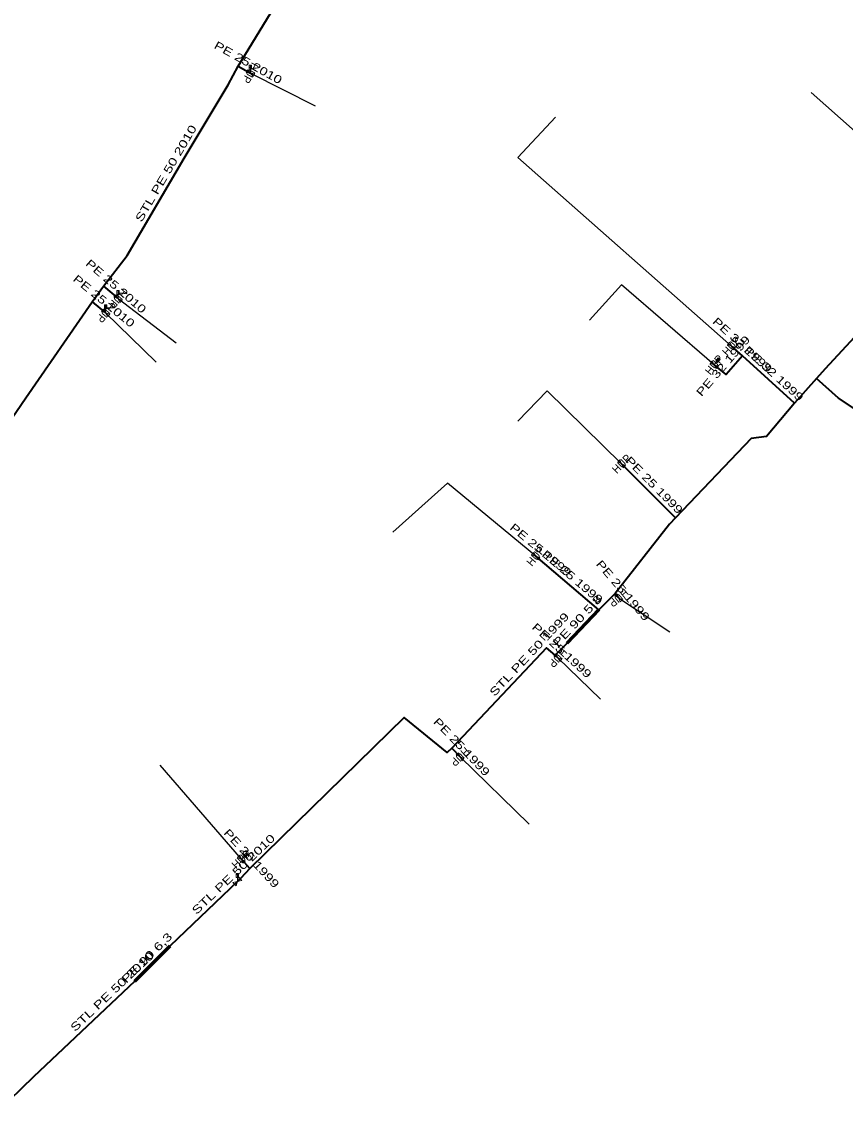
# Model space of a CAD drawing. Extents: x -737484 to -734496, y -1033882 to -1030666.
# Drawn here: x -736461.6 to -736358.7, y -1032557.9 to -1032421.6 of the extents above; entities that cross this region are included whole.
import ezdxf
from ezdxf.enums import TextEntityAlignment as Align

# ---------------------------------------------------------------- set-up
doc = ezdxf.new("R2010")
doc.units = 0
doc.header["$LTSCALE"] = 0.4
for name, color, linetype, lineweight in [('1', 7, 'Continuous', 13), ('18', 7, 'Continuous', 60), ('22', 7, 'Continuous', 25), ('5', 7, 'Continuous', 35), ('7', 7, 'Continuous', 35)]:
    doc.layers.add(name, color=color, linetype=linetype, lineweight=lineweight)
doc.layers.add('2', color=7, linetype='Continuous')

msp = doc.modelspace()

# ---------------------------------------------------------------- linework, layer by layer
at = {"layer": '1'}
for p, q in [((-736433.019, -1032428.027), (-736433.019, -1032427.527)), ((-736432.944, -1032427.452), (-736432.944, -1032427.102)), ((-736449.565, -1032456.226), (-736449.565, -1032455.726)), ((-736449.49, -1032455.651), (-736449.49, -1032455.301)), ((-736451.111, -1032457.994), (-736451.111, -1032457.494)), ((-736451.036, -1032457.419), (-736451.036, -1032457.069)), ((-736375.079, -1032464.499), (-736374.764, -1032464.11)), ((-736374.658, -1032464.099), (-736374.438, -1032463.827)), ((-736434.15, -1032526.3), (-736433.784, -1032525.959)), ((-736433.678, -1032525.962), (-736433.422, -1032525.724)), ((-736434.644, -1032529.078), (-736434.644, -1032528.578)), ((-736434.569, -1032528.503), (-736434.569, -1032528.153))]:
    msp.add_line(p, q, dxfattribs=at)
for points in [[(-736432.484, -1032428.094), (-736432.678, -1032428.444), (-736433.359, -1032427.609), (-736433.553, -1032427.959)], [(-736433.019, -1032427.027), (-736433.169, -1032427.027), (-736433.169, -1032427.527), (-736433.019, -1032427.527)], [(-736433.019, -1032427.027), (-736432.869, -1032427.027), (-736432.869, -1032427.527), (-736433.019, -1032427.527)], [(-736432.982, -1032427.065), (-736432.907, -1032427.065), (-736432.907, -1032427.49), (-736432.982, -1032427.49)], [(-736449.056, -1032456.403), (-736449.318, -1032456.704), (-736449.811, -1032455.747), (-736450.073, -1032456.048)], [(-736449.565, -1032455.226), (-736449.715, -1032455.226), (-736449.715, -1032455.726), (-736449.565, -1032455.726)], [(-736449.565, -1032455.226), (-736449.415, -1032455.226), (-736449.415, -1032455.726), (-736449.565, -1032455.726)], [(-736449.528, -1032455.264), (-736449.453, -1032455.264), (-736449.453, -1032455.689), (-736449.528, -1032455.689)], [(-736450.596, -1032458.153), (-736450.848, -1032458.464), (-736451.373, -1032457.523), (-736451.625, -1032457.834)], [(-736451.111, -1032456.994), (-736451.261, -1032456.994), (-736451.261, -1032457.494), (-736451.111, -1032457.494)], [(-736451.111, -1032456.994), (-736450.961, -1032456.994), (-736450.961, -1032457.494), (-736451.111, -1032457.494)], [(-736451.074, -1032457.032), (-736450.999, -1032457.032), (-736450.999, -1032457.457), (-736451.074, -1032457.457)], [(-736373.404, -1032461.963), (-736373.136, -1032461.665), (-736372.661, -1032462.632), (-736372.393, -1032462.334)], [(-736375.593, -1032464.339), (-736375.341, -1032464.028), (-736374.816, -1032464.969), (-736374.564, -1032464.658)], [(-736374.449, -1032463.721), (-736374.566, -1032463.627), (-736374.88, -1032464.016), (-736374.764, -1032464.11)], [(-736374.449, -1032463.721), (-736374.333, -1032463.816), (-736374.647, -1032464.204), (-736374.764, -1032464.11)], [(-736374.444, -1032463.774), (-736374.386, -1032463.821), (-736374.654, -1032464.152), (-736374.712, -1032464.104)], [(-736387.133, -1032476.666), (-736386.851, -1032476.384), (-736386.426, -1032477.373), (-736386.144, -1032477.091)], [(-736397.883, -1032488.245), (-736397.626, -1032487.939), (-736397.117, -1032488.888), (-736396.86, -1032488.582)], [(-736386.533, -1032493.874), (-736386.839, -1032494.131), (-736387.176, -1032493.108), (-736387.482, -1032493.365)], [(-736394.102, -1032501.304), (-736394.37, -1032501.602), (-736394.845, -1032500.635), (-736395.113, -1032500.933)], [(-736406.337, -1032513.709), (-736406.625, -1032513.987), (-736407.032, -1032512.99), (-736407.32, -1032513.268)], [(-736434.637, -1032526.07), (-736434.344, -1032525.797), (-736433.955, -1032526.802), (-736433.662, -1032526.529)], [(-736433.418, -1032525.618), (-736433.52, -1032525.508), (-736433.886, -1032525.849), (-736433.784, -1032525.959)], [(-736433.418, -1032525.618), (-736433.316, -1032525.727), (-736433.682, -1032526.068), (-736433.784, -1032525.959)], [(-736433.421, -1032525.67), (-736433.37, -1032525.725), (-736433.68, -1032526.015), (-736433.732, -1032525.96)], [(-736434.492, -1032528.514), (-736434.075, -1032528.946), (-736435.212, -1032529.209), (-736434.795, -1032529.641)], [(-736434.644, -1032528.078), (-736434.794, -1032528.078), (-736434.794, -1032528.578), (-736434.644, -1032528.578)], [(-736434.644, -1032528.078), (-736434.494, -1032528.078), (-736434.494, -1032528.578), (-736434.644, -1032528.578)], [(-736434.607, -1032528.116), (-736434.532, -1032528.116), (-736434.532, -1032528.541), (-736434.607, -1032528.541)]]:
    msp.add_lwpolyline(points, close=True, dxfattribs=at)
at = {"layer": '18'}
for p, q in [((-736393.429, -1032499.309), (-736389.461, -1032495.078)), ((-736447.478, -1032541.53), (-736443.04, -1032537.119))]:
    msp.add_line(p, q, dxfattribs=at)
at = {"layer": '22'}
for p, q in [((-736433.019, -1032428.027), (-736424.94, -1032432.11)), ((-736352.189, -1032440), (-736362.976, -1032430.459)), ((-736449.565, -1032456.226), (-736442.304, -1032461.77)), ((-736451.111, -1032457.994), (-736444.816, -1032464.149)), ((-736387.009, -1032493.62), (-736380.597, -1032497.881)), ((-736394.609, -1032501.119), (-736389.264, -1032506.308)), ((-736406.829, -1032513.49), (-736398.177, -1032521.901)), ((-736434.15, -1032526.3), (-736444.286, -1032514.532))]:
    msp.add_line(p, q, dxfattribs=at)
for points in [[(-736372.899, -1032462.149), (-736399.603, -1032438.602), (-736394.882, -1032433.553)], [(-736375.079, -1032464.5), (-736386.661, -1032454.521), (-736390.649, -1032458.918)], [(-736386.64, -1032476.879), (-736395.939, -1032467.752), (-736399.602, -1032471.539)], [(-736397.372, -1032488.414), (-736408.394, -1032479.274), (-736415.231, -1032485.422)]]:
    msp.add_lwpolyline(points, dxfattribs=at)
at = {"layer": '5'}
msp.add_line((-736434.259, -1032528.709), (-736434.644, -1032529.078), dxfattribs=at)
for points in [[(-736256.34, -1032354.06), (-736257.03, -1032354.95), (-736260.59, -1032359.44), (-736272.46, -1032371.63), (-736285.72, -1032384.95), (-736298.08, -1032397.54), (-736305.52, -1032405.1), (-736312.78, -1032412.28), (-736323.22, -1032423.701), (-736333.96, -1032435.45), (-736335.03, -1032436.63), (-736344.49, -1032446.8), (-736353.42, -1032456.59), (-736361.22, -1032465.02), (-736362.27, -1032466.2)], [(-736501.99, -1032518.186), (-736494.005, -1032509.824), (-736485.693, -1032501.05), (-736479.04, -1032493.131), (-736474.587, -1032487.629), (-736473.007, -1032485.735), (-736469.184, -1032480.478), (-736461.088, -1032468.614), (-736452.802, -1032456.612), (-736451.372, -1032454.659), (-736448.439, -1032450.843), (-736441.296, -1032438.651), (-736435.822, -1032429.517), (-736434.551, -1032427.173), (-736428.273, -1032416.819)], [(-736362.27, -1032466.2), (-736365.05, -1032469.29), (-736368.54, -1032473.46), (-736370.45, -1032473.71), (-736379.92, -1032483.62), (-736380.66, -1032484.4), (-736387.45, -1032493.1), (-736389.5, -1032495.12), (-736393.43, -1032499.31), (-736394.96, -1032500.8), (-736396.02, -1032499.86), (-736407.86, -1032512.41), (-736408.44, -1032512.96), (-736413.8, -1032508.58), (-736433.09, -1032527.45), (-736434.259, -1032528.709)], [(-736281.54, -1032520.32), (-736305.46, -1032504.54), (-736314.51, -1032498.76), (-736326.73, -1032490.8), (-736344.11, -1032478.91), (-736359.52, -1032468.66), (-736362.27, -1032466.2)], [(-736434.644, -1032529.078), (-736443.04, -1032537.119), (-736447.478, -1032541.53), (-736460.126, -1032553.515), (-736464.706, -1032557.917)]]:
    msp.add_lwpolyline(points, dxfattribs=at)
at = {"layer": '7'}
for p, q in [((-736434.551, -1032427.173), (-736433.019, -1032428.027)), ((-736451.372, -1032454.659), (-736449.565, -1032456.226)), ((-736452.802, -1032456.612), (-736451.111, -1032457.994)), ((-736371.55, -1032463.38), (-736372.899, -1032462.149)), ((-736365.05, -1032469.29), (-736371.55, -1032463.38)), ((-736379.92, -1032483.62), (-736386.639, -1032476.879)), ((-736397.372, -1032488.414), (-736397.425, -1032488.37)), ((-736389.5, -1032495.12), (-736397.372, -1032488.414)), ((-736387.45, -1032493.1), (-736387.008, -1032493.62)), ((-736394.96, -1032500.8), (-736394.608, -1032501.119)), ((-736407.86, -1032512.41), (-736406.829, -1032513.489)), ((-736433.09, -1032527.45), (-736434.15, -1032526.3))]:
    msp.add_line(p, q, dxfattribs=at)
msp.add_lwpolyline([(-736371.55, -1032463.38), (-736373.57, -1032465.73), (-736375.079, -1032464.499)], dxfattribs=at)

# ---------------------------------------------------------------- texts
at = {"layer": '18', "width": 1.4}
for s, rotation, p in [('PE 90 5,8', 46.837, (-736391.8092, -1032496.851)), ('PE 90 6,3', 44.825, (-736445.611, -1032538.9695))]:
    msp.add_text(s, height=1, rotation=rotation, dxfattribs=at).set_placement(p, align=Align.CENTER)
at = {"layer": '2', "width": 0.95}
for rotation, p in [(241, (-736433.4561, -1032427.7841)), (229, (-736449.9416, -1032455.8975)), (231, (-736451.4988, -1032457.6788)), (48, (-736372.5273, -1032462.4831)), (51, (-736374.6902, -1032464.8132)), (45, (-736386.2851, -1032477.2321)), (50, (-736396.9884, -1032488.7349)), (220, (-736387.3291, -1032493.2366)), (228, (-736394.9787, -1032500.7839)), (224, (-736407.1752, -1032513.1284)), (43, (-736433.8085, -1032526.665))]:
    msp.add_text('HUP', height=1, rotation=rotation, dxfattribs=at).set_placement(p, align=Align.CENTER)
at = {"layer": '5', "width": 1.4}
for s, rotation, p in [('STL PE 50 2010', 59.635, (-736443.147, -1032440.8213)), ('STL PE 50 1999', 46.667, (-736397.8122, -1032501.0311)), ('STL PE 50 2010', 43.784, (-736434.797, -1032528.5325)), ('STL PE 50 2010', 43.458, (-736449.9604, -1032543.1935))]:
    msp.add_text(s, height=1, rotation=rotation, dxfattribs=at).set_placement(p, align=Align.CENTER)
at = {"layer": '7', "width": 1.35}
for s, rotation, p in [('PE 25 2010', 330.863, (-736433.5409, -1032427.1628)), ('PE 25 2010', 319.069, (-736450.1406, -1032455.0639)), ('PE 25 2010', 320.742, (-736451.6394, -1032456.9156)), ('PE 32 1999', 317.619, (-736371.887, -1032462.3949)), ('PE 32 1999', 49.318, (-736373.5739, -1032464.9669)), ('PE 32 1999', 317.722, (-736367.9634, -1032465.9643)), ('PE 25 1999', 314.906, (-736382.9251, -1032479.896)), ('PE 25 1999', 320.301, (-736397.0789, -1032488.0062)), ('PE 25 1999', 319.573, (-736393.1112, -1032491.3857)), ('PE 25 1999', 310.365, (-736386.8482, -1032493.0352)), ('PE 25 1999', 317.816, (-736394.4478, -1032500.5888)), ('PE 25 1999', 313.697, (-736406.9828, -1032512.6036)), ('PE 25 1999', 312.668, (-736433.2515, -1032526.5356))]:
    msp.add_text(s, height=1, rotation=rotation, dxfattribs=at).set_placement(p, align=Align.CENTER)

doc.saveas('drawing.dxf')
